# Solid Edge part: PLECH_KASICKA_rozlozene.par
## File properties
Author: Acer
Template: Iso Metric Part.par
Last saved by: Acer
Revision: 41
Application: Solid Edge
Username: Acer
Typ obsahu dokumentu: 0
Density: 8027,000 kg/m^3
Accuracy: 0,990
Material Thickness: 2,00 mm
Bend Radius: 1,00 mm
Relief Width: 1,00 mm
Relief Length: 0,00 mm
Neutral Factor: 0,330
Minimum Arc Length: 0,10 mm
Deviational Tolerance: 0,10 mm
Material: Stainless Steel, 303
Face Style: Steel
Fill Style: ANSI32(Steel)
Virtual Style: ANSI32(Steel)
Grouping: Metals\Steel
LibraryName: Materials
Coef. of Thermal Exp: 1.7e-05
Thermal Conductivity: 17.0
Specific Heat: 502.0
Modulus of Elasticity: 193053196000.0
Poisson's Ratio: 0.29
Yield Stress: 255106009.0
Ultimate Stress: 579159588.0
Elongation: 0.0
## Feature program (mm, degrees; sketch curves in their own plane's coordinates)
sketch for "unnamed Protrusion 1" plane through (0, 0, 0) normal (0, 0, 1) x-axis (1, 0, 0)
  line (-50, -30) -> (50, -30)
  line (50, -30) -> (50, 30)
  line (50, 30) -> (-50, 30)
  line (-50, 30) -> (-50, -30)
  dimension (linear) = 50
  dimension (linear) = 50
extrude "unnamed Protrusion 1" add finite 60 along +normal
lofted protrusion "unnamed LoftedProtrusion 1"
sketch for "unnamed Cutout 1" plane through (0, 15.408, 79.456) normal (0, 0.8, 0.6) x-axis (-1, 0, 0)
extrude "unnamed Cutout 1" cut through along -normal
unfold "unnamed Unfold 1"
Other named dimensions: "Convert_To_Sheet_Metal_4": GapDistance = 0.02 mm
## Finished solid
Body 1: solid body, 80 faces, 170 edges, 92 vertices.
  Faces by surface: plane 74, spline 4, swept 2
  Edges by curve: line 150, curve on surface 8, intersection 8, spline 4
Body 2: solid body, 9 faces, 16 edges, 9 vertices.
  Faces by surface: plane 9
  Edges by curve: line 16
Bounding box of the edges (mm; curved faces can reach further): 311.304 x 265.060 x 210.605, from (-261.3036, -132.53, -110.6046) to (50, 132.53, 100).
Planar faces by outward normal: +x 1, +y 9, -x 1, -y 9, -z 1, oblique 62
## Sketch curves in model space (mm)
line (-85.4034, 27.98, 31.6773) -> (-92.5874, 27.98, 25.9301)
line (-85.4034, -27.9912, 31.6773) -> (-85.4034, 27.98, 31.6773)
line (-92.5874, -27.9912, 25.9301) -> (-85.4034, -27.9912, 31.6773)
line (-92.5874, 27.98, 25.9301) -> (-92.5874, -27.9912, 25.9301)
line (-178.1368, -27.98, -42.5094) -> (-170.9528, -27.98, -36.7622)
line (-178.1368, 27.9395, -42.5094) -> (-178.1368, -27.98, -42.5094)
line (-170.9528, 27.9395, -36.7622) -> (-178.1368, 27.9395, -42.5094)
line (-170.9528, -27.98, -36.7622) -> (-170.9528, 27.9395, -36.7622)
line (-162.7222, 77.845, -30.1777) -> (-162.7222, 45.9865, -30.1777)
line (-138.0171, 77.845, -10.4137) -> (-162.7222, 77.845, -30.1777)
line (-138.0171, 45.9865, -10.4137) -> (-138.0171, 77.845, -10.4137)
line (-162.7222, 45.9865, -30.1777) -> (-138.0171, 45.9865, -10.4137)
line (-103.7826, 39.3783, 16.9739) -> (-103.7826, 30.1783, 16.9739)
line (-94.304, 39.3783, 24.5568) -> (-103.7826, 39.3783, 16.9739)
line (-94.304, 30.1783, 24.5568) -> (-94.304, 39.3783, 24.5568)
line (-103.7826, 30.1783, 16.9739) -> (-94.304, 30.1783, 24.5568)
line (-169.2362, 39.381, -35.389) -> (-169.2362, 30.1783, -35.389)
line (-120.5854, 39.381, 3.5316) -> (-169.2362, 39.381, -35.389)
line (-120.5854, 30.1783, 3.5316) -> (-120.5854, 39.381, 3.5316)
line (-169.2362, 30.1783, -35.389) -> (-120.5854, 30.1783, 3.5316)
line (-120.3358, 81.4645, 3.7314) -> (-120.3358, 30.1783, 3.7314)
line (-103.6744, 81.4645, 17.0604) -> (-120.3358, 81.4645, 3.7314)
line (-103.6744, 30.1783, 17.0604) -> (-103.6744, 81.4645, 17.0604)
line (-120.3358, 30.1783, 3.7314) -> (-103.6744, 30.1783, 17.0604)
line (-138.0171, -77.845, -10.4136) -> (-138.0171, -45.9845, -10.4136)
line (-162.7237, -77.845, -30.179) -> (-138.0171, -77.845, -10.4136)
line (-162.7238, -45.9845, -30.179) -> (-162.7237, -77.845, -30.179)
line (-138.0171, -45.9845, -10.4136) -> (-162.7238, -45.9845, -30.179)
line (-94.304, -39.3783, 24.5568) -> (-94.304, -30.1783, 24.5568)
line (-169.1917, -39.3783, -35.3533) -> (-94.304, -39.3783, 24.5568)
line (-169.1917, -30.1783, -35.3533) -> (-169.1917, -39.3783, -35.3533)
line (-94.304, -30.1783, 24.5568) -> (-169.1917, -30.1783, -35.3533)
line (-100.8165, -77.845, 19.3468) -> (-100.8165, -45.9845, 19.3468)
line (-125.5232, -77.845, -0.4185) -> (-100.8165, -77.845, 19.3468)
line (-125.5232, -45.9845, -0.4185) -> (-125.5232, -77.845, -0.4185)
line (-100.8165, -45.9845, 19.3468) -> (-125.5232, -45.9845, -0.4185)
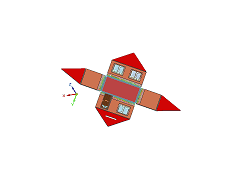
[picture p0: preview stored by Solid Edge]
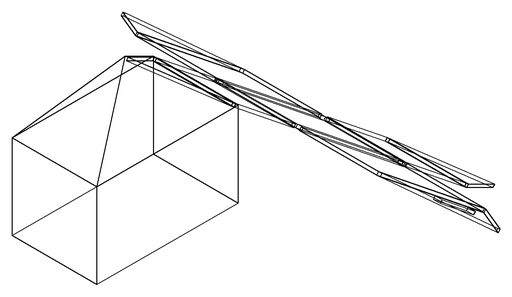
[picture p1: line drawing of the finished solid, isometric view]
